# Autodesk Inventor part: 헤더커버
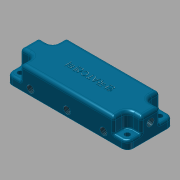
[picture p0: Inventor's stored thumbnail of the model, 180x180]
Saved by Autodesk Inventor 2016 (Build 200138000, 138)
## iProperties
Created: 2015-11
Part Number: 헤더커버
Material: 알루미늄 6061
Document SubType Name: Modeling
Designer: mduedu
Density: 2.71 g/cm^3
Appearance: 하늘색 짙음
Author: mduedu
## Parameters: d0 = 105 mm, d3 = 0, d4 = 12 mm, d5 = 12 mm, d6 = 13 mm, d7 = 0, d8 = 5 mm, d9 = 1 mm, d10 = 5 mm, d11 = 2 mm, d12 = 3 mm, d13 = 6 mm, d14 = 6 mm, d15 = 4.5 mm, d16 = 6 mm, d17 = 4 mm, d18 = 2 mm, d19 = 90 deg, d20 = 8 mm, d21 = 118 deg, d22 = 24.5 mm, d23 = 24.5 mm, d24 = 24.5 mm, d25 = 32 mm, d26 = 32 mm, d27 = 8 mm, d28 = 0, d29 = 5 mm, d32 = 120 deg, d34 = 12 mm, d35 = 8 mm, d38 = 12 mm, d39 = 120 deg, d40 = 8 mm, d43 = 5.944 mm, d44 = 6.886 mm, d45 = 0.62479 mm, d46 = 5.959 mm, d47 = 4 mm, d48 = 2 mm, d49 = 90 deg, d50 = 6.9 mm, d51 = 0, d54 = 5.944 mm, d55 = 6.886 mm, d56 = 0.62479 mm, d57 = 5.959 mm, d58 = 4 mm, d59 = 2 mm, d60 = 90 deg, d61 = 6.9 mm, d62 = 0, d65 = 5.944 mm, d66 = 6.886 mm, d67 = 0.62479 mm, d68 = 5.959 mm, d69 = 4 mm, d70 = 2 mm, d71 = 90 deg, d72 = 6.9 mm, d73 = 0, d74 = 0, d75 = 0, d76 = 0, d77 = 5 mm, d78 = 5.944 mm, d79 = 6.886 mm, d80 = 0.62479 mm, d81 = 5.959 mm, d82 = 4 mm, d83 = 2 mm, d84 = 90 deg, d85 = 6.9 mm, d86 = 0, d87 = 8 mm, d88 = 0, d89 = 0.5 mm, d90 = 0, d91 = 0, d92 = 0, d93 = 0
